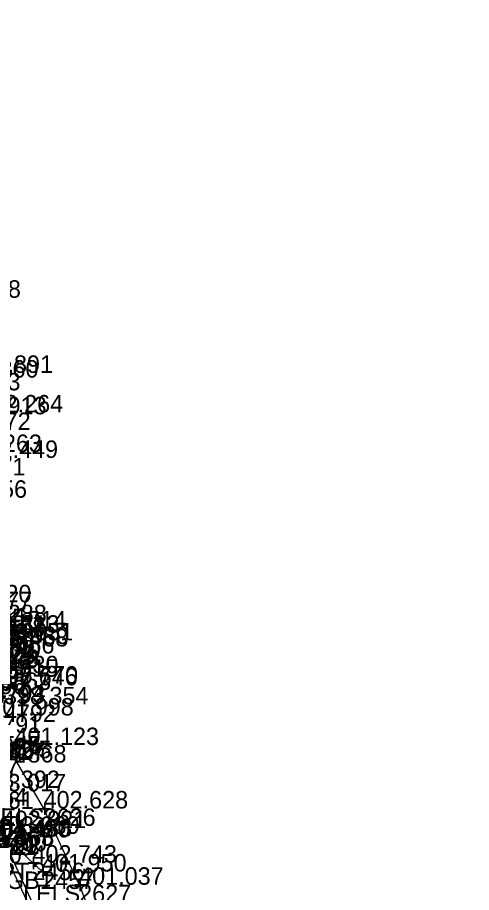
# Model space of a CAD drawing. Extents: x 1040177 to 1042343, y 1125540 to 1129143.
# Drawn here: x 1041378 to 1041637, y 1126334 to 1126834 of the extents above; entities that cross this region are included whole.
import ezdxf

# ---------------------------------------------------------------- set-up
doc = ezdxf.new("R2010")
doc.units = 0
for name, color, linetype in [('CDEFAULT', 7, 'Continuous'), ('COCOD', 7, 'Continuous'), ('COELE', 7, 'Continuous'), ('COPNT', 7, 'Continuous'), ('LAWA', 7, 'Continuous'), ('LELS', 7, 'Continuous'), ('PSU', 7, 'Continuous'), ('RGB', 7, 'Continuous'), ('UEO', 7, 'Continuous')]:
    doc.layers.add(name, color=color, linetype=linetype)

msp = doc.modelspace()

# ---------------------------------------------------------------- linework, layer by layer
at = {"layer": 'LAWA'}
for points in [[(1041361.35, 1126435.01), (1041392.46, 1126381.83)], [(1041392.46, 1126381.83), (1041412.8, 1126338.2)], [(1041412.8, 1126338.2), (1041431.75, 1126290.45)]]:
    msp.add_lwpolyline(points, dxfattribs=at)
at = {"layer": 'LELS'}
for points in [[(1041391.67, 1126381.83), (1041392.46, 1126381.83)], [(1041392.46, 1126382.62), (1041392.46, 1126381.83)], [(1041392.46, 1126381.83), (1041393.25, 1126381.83)], [(1041392.46, 1126381.83), (1041392.46, 1126381.04)], [(1041412.02, 1126338.2), (1041412.8, 1126338.2)], [(1041412.8, 1126338.99), (1041412.8, 1126338.2)], [(1041412.8, 1126338.2), (1041413.59, 1126338.2)], [(1041412.8, 1126338.2), (1041412.8, 1126337.41)]]:
    msp.add_lwpolyline(points, dxfattribs=at)
at = {"layer": 'PSU'}
msp.add_lwpolyline([(1041533.7, 1126007.23), (1041534.28, 1126010.3), (1041513.25, 1126053.33), (1041492.46, 1126099.13), (1041471.38, 1126143.37), (1041449.72, 1126187.11), (1041428.39, 1126232), (1041407.07, 1126276.87), (1041386.16, 1126322.29), (1041364.66, 1126367.32), (1041342.25, 1126412.26), (1041320.24, 1126456.9), (1041299.25, 1126502.25), (1041286.53, 1126533.1)], dxfattribs=at)
at = {"layer": 'RGB'}
msp.add_lwpolyline([(1041375.92, 1126361.42), (1041379.85, 1126357.04), (1041383.96, 1126352.85), (1041386.1, 1126350.83), (1041391.59, 1126345.78)], dxfattribs=at)
at = {"layer": 'UEO'}
msp.add_lwpolyline([(1041637.25, 1125710.1), (1041581.42, 1125830.46), (1041545.48, 1125904.81), (1041532.57, 1125930.38), (1041527.11, 1125942.48), (1041492, 1126018.02), (1041512.6, 1126063.57), (1041430.46, 1126236.16), (1041391.01, 1126316.77), (1041348.62, 1126410.54), (1041292.44, 1126530.43), (1041208.26, 1126709.96), (1041219.88, 1126771.49), (1041151.41, 1126922.21), (1041079.71, 1127080.15)], dxfattribs=at)

# ---------------------------------------------------------------- texts
at = {"layer": 'CDEFAULT'}
for height, p in [(10, (1041372.54, 1126413.11)), (10, (1041389.19, 1126376.83)), (0.0781, (1041392.44, 1126381.79)), (10, (1041382.83, 1126345.83)), (0.0781, (1041386.08, 1126350.79)), (10, (1041388.33, 1126340.78)), (0.0781, (1041391.57, 1126345.74)), (10, (1041409.54, 1126333.2)), (0.0781, (1041412.79, 1126338.16))]:
    msp.add_text('+', height=height, dxfattribs=at).set_placement(p)
at = {"layer": 'COCOD'}
for s, height, p in [('UEO1', 10, (1041345.89, 1126408.11)), ('LELS', 10, (1041360.34, 1126371.83)), ('LELS LAWA ST', 0.0781, (1041391.84, 1126381.75)), ('RGB1 PT', 10, (1041327.13, 1126340.83)), ('RGB1 PT', 0.0781, (1041385.74, 1126350.75)), ('RGB1', 10, (1041361.28, 1126335.78)), ('RGB1', 0.0781, (1041391.41, 1126345.7)), ('LELS', 10, (1041380.68, 1126328.2)), ('LELS LAWA JPT 2304', 0.0781, (1041411.87, 1126338.12))]:
    msp.add_text(s, height=height, dxfattribs=at).set_placement(p)
at = {"layer": 'COELE'}
for s, height, p in [('401.138', 10, (1041331.13, 1126673.98)), ('401.860', 10, (1041341.2, 1126628.29)), ('401.891', 10, (1041349.49, 1126631.01)), ('401.913', 10, (1041345.81, 1126607.31)), ('402.264', 10, (1041355.3, 1126608.36)), ('402.263', 10, (1041343.16, 1126585.73)), ('402.449', 10, (1041352.38, 1126582.35)), ('402.856', 10, (1041334.64, 1126559.57)), ('400.620', 10, (1041337.16, 1126499.74)), ('398.177', 10, (1041337.5, 1126495.77)), ('397.554', 10, (1041333.9, 1126486.59)), ('398.288', 10, (1041345.92, 1126488.36)), ('395.965', 10, (1041333.52, 1126486.04)), ('398.313', 10, (1041353.29, 1126482.37)), ('401.014', 10, (1041357.15, 1126484.76)), ('396.231', 10, (1041337.59, 1126477.16)), ('396.608', 10, (1041345.09, 1126480.29)), ('397.467', 10, (1041345.13, 1126481.25)), ('399.051', 10, (1041361.08, 1126477.94)), ('396.468', 10, (1041358.27, 1126474.52)), ('398.080', 10, (1041358.63, 1126475.84)), ('396.566', 10, (1041350.29, 1126470.43)), ('399.439', 10, (1041341.47, 1126461.95)), ('396.378', 10, (1041341.64, 1126462.81)), ('402.075', 10, (1041337.22, 1126458.6)), ('397.315', 10, (1041352.49, 1126457.19)), ('396.730', 10, (1041352.63, 1126459.16)), ('397.646', 10, (1041363.62, 1126452.27)), ('396.770', 10, (1041363.84, 1126453.24)), ('401.863', 10, (1041348.4, 1126449.63)), ('398.354', 10, (1041369.77, 1126441.37)), ('401.998', 10, (1041361.35, 1126435.01)), ('401.123', 10, (1041375.81, 1126418.11)), ('403.934', 10, (1041342.25, 1126412.26)), ('403.545', 10, (1041342.88, 1126413.3)), ('404.242', 10, (1041338.32, 1126410.39)), ('404.216', 10, (1041339.18, 1126410.88)), ('403.727', 10, (1041345.12, 1126409.49)), ('402.775', 10, (1041348.62, 1126410.54)), ('403.392', 10, (1041353.42, 1126393.51)), ('403.017', 10, (1041357.01, 1126391.6)), ('402.628', 10, (1041392.46, 1126381.83)), ('402.628', 0.0781, (1041392.46, 1126381.83)), ('403.930', 10, (1041364.66, 1126367.32)), ('402.921', 10, (1041368.53, 1126370.58)), ('404.490', 10, (1041359.47, 1126365.26)), ('404.488', 10, (1041360.46, 1126365.77)), ('404.668', 10, (1041350.24, 1126360.44)), ('403.979', 10, (1041337.87, 1126354.98)), ('404.280', 10, (1041340.82, 1126356.16)), ('402.743', 10, (1041386.1, 1126350.83)), ('401.950', 10, (1041391.59, 1126345.78)), ('402.743', 0.0781, (1041386.1, 1126350.83)), ('401.037', 10, (1041412.8, 1126338.2)), ('401.950', 0.0781, (1041391.59, 1126345.78)), ('401.037', 0.0781, (1041412.8, 1126338.2))]:
    msp.add_text(s, height=height, dxfattribs=at).set_placement(p)
at = {"layer": 'COPNT'}
for s, height, p in [('2473', 10, (1041349.49, 1126621.01)), ('2472', 10, (1041355.3, 1126598.36)), ('2471', 10, (1041352.38, 1126572.35)), ('4839', 10, (1041353.29, 1126472.37)), ('4823', 10, (1041357.15, 1126474.76)), ('4840', 10, (1041361.08, 1126467.94)), ('4825', 10, (1041358.27, 1126464.52)), ('4824', 10, (1041358.63, 1126465.84)), ('4841', 10, (1041350.29, 1126460.43)), ('4796', 10, (1041352.49, 1126447.19)), ('4795', 10, (1041352.63, 1126449.16)), ('4793', 10, (1041363.62, 1126442.27)), ('4794', 10, (1041363.84, 1126443.24)), ('4792', 10, (1041369.77, 1126431.37)), ('4791', 10, (1041361.35, 1126425.01)), ('4868', 10, (1041375.81, 1126408.11)), ('4867', 10, (1041348.62, 1126400.54)), ('2454', 10, (1041353.42, 1126383.51)), ('2461', 10, (1041357.01, 1126381.6)), ('2626', 0.0781, (1041392.46, 1126381.75)), ('2626', 10, (1041392.46, 1126371.83)), ('2460', 10, (1041364.66, 1126357.32)), ('2455', 10, (1041368.53, 1126360.58)), ('2121', 10, (1041359.47, 1126355.26)), ('2122', 10, (1041360.46, 1126355.77)), ('2120', 10, (1041350.24, 1126350.44)), ('2456', 0.0781, (1041386.1, 1126350.75)), ('2456', 10, (1041386.1, 1126340.83)), ('2457', 0.0781, (1041391.59, 1126345.7)), ('2457', 10, (1041391.59, 1126335.78)), ('2627', 0.0781, (1041412.8, 1126338.12)), ('2627', 10, (1041412.8, 1126328.2))]:
    msp.add_text(s, height=height, dxfattribs=at).set_placement(p)

doc.saveas('drawing.dxf')
